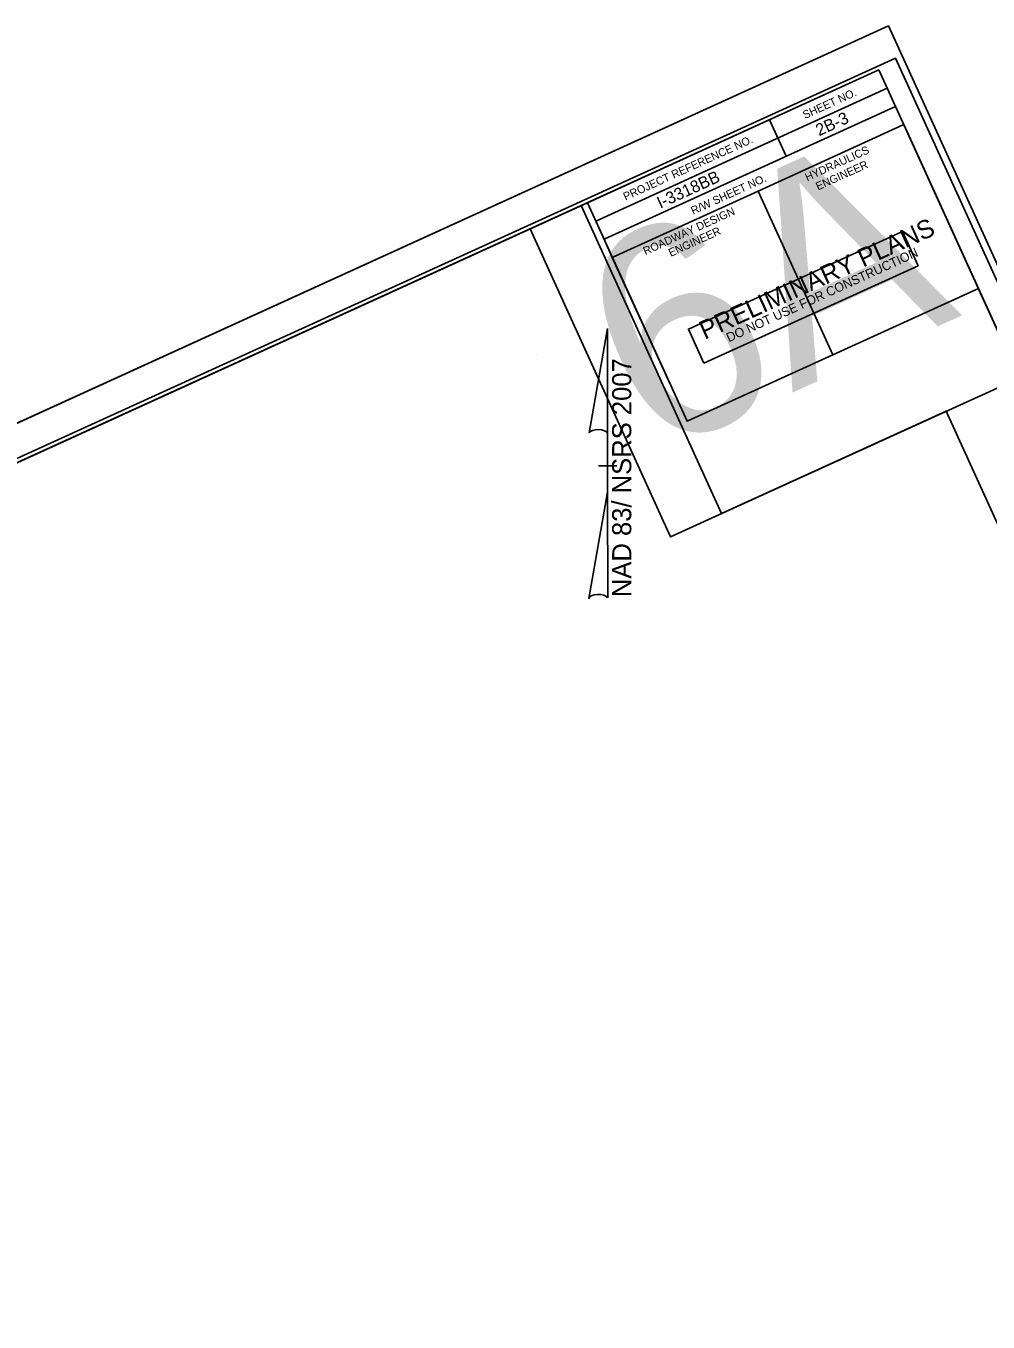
# Model space of a CAD drawing. Extents: x 2249053 to 2251039, y 663030 to 664800.
# Drawn here: x 2250046 to 2250647, y 663915 to 664725 of the extents above; entities that cross this region are included whole.
import ezdxf

# ---------------------------------------------------------------- set-up
doc = ezdxf.new("R2010")
doc.units = 0
for name, color, linetype in [('Prop North Arrow NAD83 for Plan Sheets CELL', 7, 'Continuous'), ('Sheet Clip Boundary CELL', 7, 'Continuous'), ('Sheet Cutting Line CELL', 7, 'Continuous'), ('Sheet Data Field CELL', 7, 'Continuous'), ('Sheet Layout Plan Border', 7, 'Continuous'), ('Sheet North Arrow Point CELL', 7, 'Continuous'), ('Sheet Plan CELL', 7, 'Continuous'), ('Sheet Plan Layout CELL', 7, 'Continuous'), ('Sheet Plot Border Inside CELL', 7, 'Continuous'), ('Sheet Plot Border Outside CELL', 7, 'Continuous'), ('Sheet Sticker Preliminary CELL', 7, 'Continuous')]:
    doc.layers.add(name, color=color, linetype=linetype)

msp = doc.modelspace()

# ---------------------------------------------------------------- linework, layer by layer
at = {"layer": 'Prop North Arrow NAD83 for Plan Sheets CELL'}
for p, q in [((2250397.83, 664470.59), (2250409.37, 664535.77)), ((2250409.44, 664535.77), (2250409.37, 664535.77)), ((2250409.44, 664535.77), (2250409.37, 664535.77)), ((2250409.44, 664535.77), (2250409.44, 664468.55)), ((2250409.44, 664433.68), (2250409.44, 664470.52)), ((2250409.44, 664468.55), (2250409.44, 664470.45)), ((2250403.81, 664449.99), (2250403.74, 664449.99)), ((2250408.8, 664449.99), (2250403.81, 664449.99)), ((2250403.88, 664449.99), (2250415.13, 664449.99)), ((2250409.44, 664433.68), (2250397.69, 664367.23)), ((2250409.51, 664367.51), (2250409.44, 664433.68))]:
    msp.add_line(p, q, dxfattribs=at)
for centre, start_param, end_param in [((2250403.65, 664469.89), 0.216388, 2.908219), ((2250403.65, 664367), 0.201328, 3.141593)]:
    msp.add_ellipse(centre, major_axis=(5.95, -0.04), ratio=0.461098, start_param=start_param, end_param=end_param, dxfattribs=at)
at = {"layer": 'Sheet Clip Boundary CELL'}
msp.add_lwpolyline([(2249425.27, 663908.72), (2249673.42, 663362.44), (2249698.31, 663307.82), (2249773.57, 663342.12), (2249795.76, 663293.34), (2249720.63, 663258.85), (2249760.8, 663170.69), (2250968.75, 663721.13), (2250621.05, 664484.16), (2250480.7, 664420.21), (2250393.01, 664612.65), (2249259.38, 664096.08)], close=True, dxfattribs=at)
at = {"layer": 'Sheet Cutting Line CELL'}
msp.add_line((2250585, 664724.85), (2249053.06, 664026.77), dxfattribs=at)
at = {"layer": 'Sheet Layout Plan Border'}
msp.add_lwpolyline([(2249694.77, 663140.6), (2250968.75, 663721.13), (2250621.05, 664484.16), (2250448.83, 664405.68), (2250361.13, 664598.13), (2249259.38, 664096.08)], close=True, dxfattribs=at)
at = {"layer": 'Sheet North Arrow Point CELL'}
msp.add_line((2250365.12, 664519.79), (2250365.12, 664519.79), dxfattribs=at)
msp.add_line((2250365.12, 664519.79), (2250365.12, 664519.79), dxfattribs=at)
at = {"layer": 'Sheet Plan CELL'}
for p, q in [((2250402, 664602.97), (2250584.05, 664685.92)), ((2250407.21, 664591.57), (2250589.23, 664674.54)), ((2250407.21, 664591.57), (2250589.23, 664674.54)), ((2250510.6, 664666.17), (2250521.01, 664643.44)), ((2250503.43, 664621.69), (2250550.08, 664519.36)), ((2250407.21, 664591.57), (2250412.39, 664580.21))]:
    msp.add_line(p, q, dxfattribs=at)
for points in [[(2250578.88, 664697.35), (2249213.88, 664075.35), (2249649.27, 663119.87), (2251014.25, 663741.87)], [(2250396.81, 664614.4), (2250578.88, 664697.35), (2250589.23, 664674.54), (2250407.21, 664591.57)], [(2250503.43, 664621.69), (2250594.42, 664663.17), (2250641.08, 664560.79), (2250550.09, 664519.31)], [(2250412.39, 664580.21), (2250503.43, 664621.69), (2250550.09, 664519.31), (2250459.05, 664477.85)], [(2249649.27, 663119.87), (2249213.87, 664075.31), (2250396.81, 664614.4), (2250459.05, 664477.85), (2250641.08, 664560.79), (2251014.25, 663741.87)]]:
    msp.add_lwpolyline(points, close=True, dxfattribs=at)
at = {"layer": 'Sheet Plan Layout CELL'}
for points in [[(2250448.83, 664405.68), (2250666.56, 664504.9), (2250578.89, 664697.36), (2250361.13, 664598.13)], [(2249213.87, 664075.31), (2249649.27, 663119.87), (2251014.24, 663741.86), (2250666.54, 664504.89), (2250448.83, 664405.68), (2250361.13, 664598.13)]]:
    msp.add_lwpolyline(points, close=True, dxfattribs=at)
at = {"layer": 'Sheet Plot Border Inside CELL'}
msp.add_lwpolyline([(2249510.65, 663053.94), (2251026.65, 663744.77), (2250589.2, 664704.79), (2249073.18, 664013.96)], close=True, dxfattribs=at)
at = {"layer": 'Sheet Plot Border Outside CELL'}
msp.add_lwpolyline([(2249507.11, 663030.35), (2251039.05, 663728.43), (2250585, 664724.85), (2249053.06, 664026.77)], close=True, dxfattribs=at)
at = {"layer": 'Sheet Sticker Preliminary CELL'}
msp.add_lwpolyline([(2250469.64, 664514.07), (2250459.9, 664535.45), (2250593.66, 664596.41), (2250603.41, 664575.02)], close=True, dxfattribs=at)

# ---------------------------------------------------------------- texts
at = {"layer": 'Prop North Arrow NAD83 for Plan Sheets CELL'}
msp.add_text('NAD 83/ NSRS 2007', height=11.9532, rotation=90, dxfattribs=at).set_placement((2250424.23, 664368))
at = {"layer": 'Sheet Data Field CELL'}
for s, p in [('2B-3', (2250541.56, 664655.9)), ('I-3318BB', (2250442.35, 664610.62))]:
    msp.add_text(s, height=7.5, rotation=24.49795, dxfattribs=at).set_placement(p)
at = {"layer": 'Sheet Plan CELL'}
for s, height, p in [('SHEET NO.', 5, (2250532.75, 664666.63)), ('PROJECT REFERENCE NO.', 5.0001, (2250420.63, 664615.67)), ('HYDRAULICS', 5, (2250534.17, 664627.71)), ('ENGINEER', 5, (2250540.9, 664622.02)), ('R/W SHEET NO.', 5.0001, (2250462.89, 664606.85)), ('ROADWAY DESIGN', 5.0001, (2250433.05, 664581.6)), ('ENGINEER', 5, (2250448.9, 664580.54))]:
    msp.add_text(s, height=height, rotation=24.49795, dxfattribs=at).set_placement(p)
at = {"layer": 'Sheet Plan Layout CELL'}
msp.add_text('6A', height=131.25, rotation=24.49794, dxfattribs=at).set_placement((2250435.87, 664455.17))
at = {"layer": 'Sheet Sticker Preliminary CELL'}
for s, height, p in [('PRELIMINARY PLANS', 11.52, (2250470.1, 664528.73)), ('DO NOT USE FOR CONSTRUCTION', 5.76, (2250485.22, 664527.16))]:
    msp.add_text(s, height=height, rotation=24.49794, dxfattribs=at).set_placement(p)

doc.saveas('drawing.dxf')
